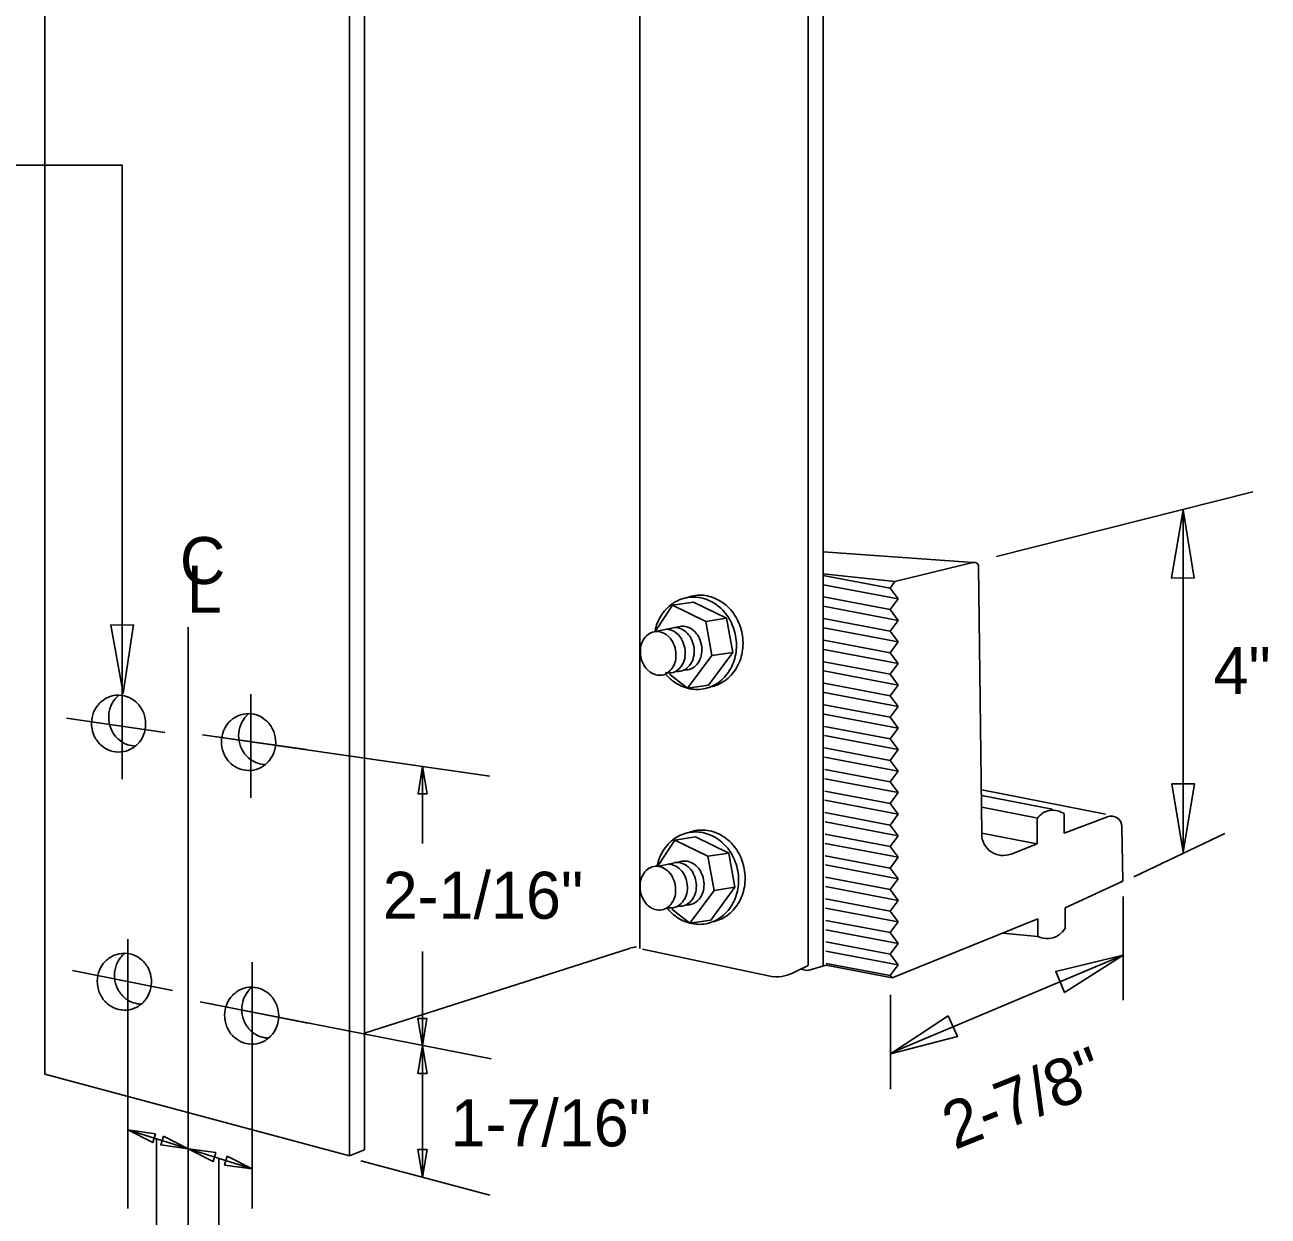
# Model space of a CAD drawing. Extents: x 12.3 to 19.6, y 5.9 to 16.2.
# Drawn here: x 17.486 to 19.073, y 9.472 to 10.993 of the extents above; entities that cross this region are included whole.
import ezdxf

# ---------------------------------------------------------------- set-up
doc = ezdxf.new("R2010")
doc.units = 0
for name, color, linetype in [('DETL-DIMS', 7, 'Continuous'), ('DETL-LINE', 7, 'Continuous'), ('DETL-NOTE', 7, 'Continuous')]:
    doc.layers.add(name, color=color, linetype=linetype)

msp = doc.modelspace()

# ---------------------------------------------------------------- linework, layer by layer
at = {"layer": 'DETL-DIMS'}
for p, q in [((17.61, 10.8139), (17.3733, 10.8139)), ((17.61, 10.8139), (17.61, 10.0298)), ((18.7263, 10.3141), (19.0536, 10.3965)), ((18.9648, 9.9352), (18.9648, 10.3742)), ((17.6945, 10.224), (17.6945, 9.4278)), ((17.7745, 10.1385), (17.7745, 10.0062)), ((17.5391, 10.1078), (17.6645, 10.0897)), ((17.7127, 10.0867), (18.0795, 10.0336)), ((17.9937, 9.9479), (17.9937, 10.0463)), ((19.0179, 9.9605), (18.9016, 9.9052)), ((18.8881, 9.88), (18.8881, 9.7477)), ((17.6174, 9.8256), (17.6174, 9.4821)), ((17.9937, 9.5218), (17.9937, 9.8101)), ((17.7761, 9.7964), (17.7761, 9.4821)), ((18.5909, 9.6803), (18.8881, 9.8051)), ((17.5465, 9.7855), (17.6743, 9.7601)), ((18.5909, 9.7546), (18.5909, 9.6343)), ((17.7097, 9.7456), (18.0811, 9.673)), ((17.6174, 9.5823), (17.7761, 9.5325)), ((17.6539, 9.5709), (17.6539, 9.3091)), ((17.7336, 9.5458), (17.7336, 9.4046)), ((18.0795, 9.499), (17.915, 9.5429))]:
    msp.add_line(p, q, dxfattribs=at)
for points in [[(18.9789, 10.2866), (18.9498, 10.2868), (18.9648, 10.3739)], [(17.6246, 10.2271), (17.5955, 10.2266), (17.6114, 10.1396)], [(17.9996, 10.0111), (17.9879, 10.0111), (17.9937, 10.0463)], [(18.9503, 10.0239), (18.9794, 10.0239), (18.9648, 9.9366)], [(18.8134, 9.7577), (18.8021, 9.7845), (18.8881, 9.8051)], [(17.9993, 9.7246), (17.9876, 9.7246), (17.9935, 9.6894)], [(18.6648, 9.728), (18.6766, 9.7014), (18.5909, 9.6794)], [(17.9994, 9.6543), (17.9877, 9.6543), (17.9935, 9.6894)], [(17.6527, 9.5773), (17.6492, 9.5661), (17.6174, 9.5822)], [(17.6628, 9.5742), (17.6593, 9.563), (17.6945, 9.5581)], [(17.7298, 9.5532), (17.7263, 9.542), (17.6945, 9.5581)], [(17.9995, 9.557), (17.9877, 9.557), (17.9937, 9.5218)], [(17.7443, 9.5486), (17.7408, 9.5374), (17.7761, 9.5325)]]:
    msp.add_lwpolyline(points, close=True, dxfattribs=at)
at = {"layer": 'DETL-LINE'}
for p, q in [((18.2711, 14.267), (18.2711, 9.8136)), ((18.486, 10.0267), (18.486, 13.1634)), ((17.9004, 9.5491), (17.9004, 13.1563)), ((17.9193, 9.5567), (17.9193, 13.1351)), ((17.5112, 9.6534), (17.5112, 13.1068)), ((18.5051, 9.7915), (18.5051, 13.0785)), ((18.6964, 10.3064), (18.5051, 10.3202)), ((18.6964, 10.3064), (18.5968, 10.2821)), ((18.5968, 10.2821), (18.5053, 10.2922)), ((18.5906, 10.2738), (18.5053, 10.29)), ((18.7075, 9.96), (18.7036, 10.3012)), ((18.6009, 10.26), (18.5054, 10.2782)), ((18.5906, 10.2738), (18.5968, 10.2821)), ((18.6009, 10.26), (18.5906, 10.2738)), ((18.3395, 10.256), (18.3129, 10.252)), ((18.3395, 10.256), (18.3819, 10.2353)), ((18.5906, 10.2463), (18.5055, 10.2625)), ((18.5906, 10.2463), (18.6009, 10.26)), ((18.2908, 10.2184), (18.3129, 10.252)), ((18.3129, 10.252), (18.3552, 10.2314)), ((18.6009, 10.2325), (18.5056, 10.2507)), ((18.6009, 10.2325), (18.5906, 10.2463)), ((18.3224, 10.2249), (18.2908, 10.2184)), ((18.3819, 10.2353), (18.3552, 10.2314)), ((18.3552, 10.2314), (18.3631, 10.1878)), ((18.3819, 10.2353), (18.3898, 10.1918)), ((18.5906, 10.2188), (18.5057, 10.2349)), ((18.6009, 10.2051), (18.5058, 10.2231)), ((18.5906, 10.2188), (18.6009, 10.2325)), ((18.5906, 10.1913), (18.5059, 10.2074)), ((18.6009, 10.2051), (18.5906, 10.2188)), ((18.3898, 10.1918), (18.3588, 10.1499)), ((18.3898, 10.1918), (18.3631, 10.1878)), ((18.6009, 10.1776), (18.506, 10.1956)), ((18.5906, 10.1913), (18.6009, 10.2051)), ((18.6009, 10.1776), (18.5906, 10.1913)), ((18.3631, 10.1878), (18.3321, 10.146)), ((18.5906, 10.1638), (18.5061, 10.1799)), ((18.5906, 10.1638), (18.6009, 10.1776)), ((18.3321, 10.146), (18.309, 10.1639)), ((18.6009, 10.1501), (18.5061, 10.1681)), ((18.6009, 10.1501), (18.5906, 10.1638)), ((18.3588, 10.1499), (18.3321, 10.146)), ((18.5906, 10.1363), (18.5063, 10.1524)), ((18.5906, 10.1363), (18.6009, 10.1501)), ((18.6009, 10.1226), (18.5063, 10.1406)), ((18.6009, 10.1226), (18.5906, 10.1363)), ((18.5906, 10.1089), (18.5065, 10.1249)), ((18.6009, 10.0951), (18.5065, 10.1131)), ((18.5906, 10.1089), (18.6009, 10.1226)), ((18.5906, 10.0814), (18.5067, 10.0973)), ((18.6009, 10.0951), (18.5906, 10.1089)), ((17.7127, 10.0867), (17.8454, 10.0676)), ((18.6009, 10.0676), (18.5067, 10.0855)), ((18.5906, 10.0814), (18.6009, 10.0951)), ((18.6009, 10.0676), (18.5906, 10.0814)), ((18.5906, 10.0539), (18.5069, 10.0698)), ((18.5906, 10.0539), (18.6009, 10.0676)), ((18.6009, 10.0402), (18.5069, 10.058)), ((18.6009, 10.0402), (18.5906, 10.0539)), ((18.5906, 10.0264), (18.5071, 10.0423)), ((18.5906, 10.0264), (18.6009, 10.0402)), ((18.486, 10.0267), (18.486, 9.7922)), ((18.6009, 10.0127), (18.5071, 10.0305)), ((18.6009, 10.0127), (18.5906, 10.0264)), ((18.5906, 9.9989), (18.5072, 10.0148)), ((18.6009, 9.9852), (18.5073, 10.003)), ((18.5906, 9.9989), (18.6009, 10.0127)), ((18.8658, 9.9852), (18.7075, 10.0162)), ((18.7976, 9.9916), (18.7075, 10.0092)), ((18.5906, 9.9714), (18.5074, 9.9872)), ((18.6009, 9.9852), (18.5906, 9.9989)), ((18.5906, 9.9714), (18.6009, 9.9852)), ((18.777, 9.9805), (18.7075, 9.9941)), ((18.813, 9.9611), (18.813, 9.9855)), ((18.6009, 9.9577), (18.5075, 9.9754)), ((18.6009, 9.9577), (18.5906, 9.9714)), ((18.7783, 9.9475), (18.7783, 9.9795)), ((18.868, 9.9819), (18.813, 9.9611)), ((18.8877, 9.8998), (18.8866, 9.9693)), ((18.3423, 9.9562), (18.3156, 9.9522)), ((18.3423, 9.9562), (18.3846, 9.9355)), ((18.5906, 9.944), (18.5076, 9.9597)), ((18.5906, 9.944), (18.6009, 9.9577)), ((18.7779, 9.9473), (18.7075, 9.9611)), ((18.2936, 9.9186), (18.3156, 9.9522)), ((18.3156, 9.9522), (18.3579, 9.9316)), ((18.6009, 9.9302), (18.5077, 9.9479)), ((18.6009, 9.9302), (18.5906, 9.944)), ((18.7783, 9.9475), (18.745, 9.9344)), ((18.3252, 9.9251), (18.2936, 9.9186)), ((18.3846, 9.9355), (18.3579, 9.9316)), ((18.3579, 9.9316), (18.3659, 9.888)), ((18.3846, 9.9355), (18.3925, 9.8919)), ((18.5906, 9.9165), (18.5078, 9.9322)), ((18.5906, 9.9165), (18.6009, 9.9302)), ((18.6009, 9.9027), (18.5079, 9.9204)), ((18.6009, 9.9027), (18.5906, 9.9165)), ((18.3925, 9.8919), (18.3616, 9.8501)), ((18.3925, 9.8919), (18.3659, 9.888)), ((18.5906, 9.889), (18.508, 9.9047)), ((18.6009, 9.8752), (18.5081, 9.8929)), ((18.5906, 9.889), (18.6009, 9.9027)), ((18.8877, 9.8998), (18.8139, 9.8658)), ((18.3659, 9.888), (18.3349, 9.8461)), ((18.5906, 9.8615), (18.5082, 9.8772)), ((18.6009, 9.8752), (18.5906, 9.889)), ((18.5906, 9.8615), (18.6009, 9.8752)), ((18.3349, 9.8461), (18.3118, 9.8641)), ((18.6009, 9.8478), (18.5083, 9.8654)), ((18.6009, 9.8478), (18.5906, 9.8615)), ((18.8139, 9.8658), (18.8139, 9.8389)), ((18.3616, 9.8501), (18.3349, 9.8461)), ((18.5906, 9.834), (18.5084, 9.8496)), ((18.5906, 9.834), (18.6009, 9.8478)), ((18.7792, 9.8518), (18.5932, 9.7765)), ((18.7792, 9.8518), (18.7792, 9.829)), ((18.6009, 9.8203), (18.5085, 9.8378)), ((18.6009, 9.8203), (18.5906, 9.834)), ((18.7792, 9.829), (18.7339, 9.8335)), ((18.258, 9.8139), (17.9193, 9.7055)), ((18.2743, 9.8128), (18.4412, 9.7778)), ((18.5906, 9.8065), (18.5086, 9.8221)), ((18.6009, 9.7928), (18.5087, 9.8103)), ((18.5906, 9.8065), (18.6009, 9.8203)), ((18.5906, 9.7791), (18.5088, 9.7946)), ((18.6009, 9.7928), (18.5906, 9.8065)), ((18.486, 9.7922), (18.4693, 9.784)), ((18.4855, 9.7858), (18.4758, 9.7872)), ((18.5088, 9.7926), (18.4855, 9.7858)), ((18.5932, 9.7765), (18.5088, 9.7926)), ((18.5906, 9.7791), (18.6009, 9.7928)), ((18.5906, 9.7791), (18.5932, 9.7765)), ((17.7097, 9.7456), (17.847, 9.7184)), ((17.9004, 9.5491), (17.5112, 9.6534)), ((17.9004, 9.5491), (17.9193, 9.5567))]:
    msp.add_line(p, q, dxfattribs=at)
for centre, radius, start, end in [((18.6981, 10.3012), 0.0055, 0, 108.2049), ((18.3395, 10.2159), 0.0465, 100.2985, 125.3838), ((18.3479, 10.2183), 0.0465, 100.2985, 111.3926), ((18.3395, 10.2159), 0.0465, 75.2131, 100.2985), ((18.3479, 10.2183), 0.0465, 75.2131, 100.2985), ((18.3377, 10.2093), 0.0533, 51.8022, 75.2131), ((18.3461, 10.2117), 0.0533, 51.8022, 75.2131), ((18.3434, 10.2104), 0.0533, 125.3838, 148.7948), ((18.334, 10.2046), 0.0593, 30.427, 51.8022), ((18.3424, 10.207), 0.0593, 30.427, 51.8022), ((18.3485, 10.2073), 0.0593, 148.7948, 168.1028), ((18.3159, 10.2052), 0.0183, 73.0064, 92.4483), ((18.3144, 10.2001), 0.0236, 49.0558, 73.0064), ((18.3257, 10.207), 0.0183, 73.0064, 100.2985), ((18.3241, 10.2019), 0.0236, 49.0558, 73.0064), ((18.3276, 10.2008), 0.0668, 10.2985, 30.427), ((18.336, 10.2033), 0.0668, 10.2985, 30.427), ((18.3003, 10.1936), 0.0286, 151.5411, 171.905), ((18.296, 10.196), 0.0236, 127.5906, 151.5411), ((18.2927, 10.2002), 0.0183, 100.2985, 127.5906), ((18.2927, 10.2002), 0.0183, 73.0064, 100.2985), ((18.2911, 10.1951), 0.0236, 49.0558, 73.0064), ((18.3045, 10.2031), 0.0183, 73.0064, 88.18), ((18.2879, 10.1914), 0.0286, 28.6919, 49.0558), ((18.303, 10.198), 0.0236, 49.0558, 73.0064), ((18.2997, 10.1943), 0.0286, 28.6919, 49.0558), ((18.2941, 10.1912), 0.0349, 10.2985, 28.6919), ((18.3111, 10.1964), 0.0286, 28.6919, 49.0558), ((18.3055, 10.1933), 0.0349, 10.2985, 28.6919), ((18.3209, 10.1981), 0.0286, 28.6919, 49.0558), ((18.3153, 10.1951), 0.0349, 10.2985, 28.6919), ((18.3276, 10.2008), 0.0668, 350.1699, 10.2985), ((18.336, 10.2033), 0.0668, 350.1699, 10.2985), ((18.3066, 10.1927), 0.0349, 171.905, 190.2985), ((18.2823, 10.1883), 0.0349, 10.2985, 28.6919), ((18.2823, 10.1883), 0.0349, 351.905, 10.2985), ((18.2941, 10.1912), 0.0349, 351.905, 10.2985), ((18.3055, 10.1933), 0.0349, 351.905, 10.2985), ((18.3153, 10.1951), 0.0349, 351.905, 10.2985), ((18.3434, 10.202), 0.0593, 328.7948, 350.1699), ((18.3066, 10.1927), 0.0349, 190.2985, 208.6919), ((18.301, 10.1897), 0.0286, 208.6919, 229.0558), ((18.2886, 10.1874), 0.0286, 331.5411, 351.905), ((18.3048, 10.188), 0.0236, 307.5906, 331.5411), ((18.3005, 10.1903), 0.0286, 331.5411, 351.905), ((18.3162, 10.19), 0.0236, 307.5906, 331.5411), ((18.3119, 10.1924), 0.0286, 331.5411, 351.905), ((18.326, 10.1918), 0.0236, 307.5906, 331.5411), ((18.3216, 10.1942), 0.0286, 331.5411, 351.905), ((18.335, 10.1996), 0.0593, 328.7948, 350.1699), ((18.2978, 10.1859), 0.0236, 229.0558, 253.0064), ((18.2962, 10.1808), 0.0183, 253.0064, 280.2985), ((18.2962, 10.1808), 0.0183, 280.2985, 307.5906), ((18.3494, 10.2022), 0.0593, 218.8502, 231.8022), ((18.3081, 10.1837), 0.0183, 256.2344, 280.2985), ((18.293, 10.1851), 0.0236, 307.5906, 331.5411), ((18.3081, 10.1837), 0.0183, 280.2985, 307.5906), ((18.3195, 10.1858), 0.0183, 261.8081, 280.2985), ((18.3195, 10.1858), 0.0183, 280.2985, 307.5906), ((18.3292, 10.1876), 0.0183, 264.5248, 280.2985), ((18.3292, 10.1876), 0.0183, 280.2985, 307.5906), ((18.3401, 10.1965), 0.0533, 305.3838, 328.7948), ((18.3485, 10.1989), 0.0533, 305.3838, 328.7948), ((18.3457, 10.1975), 0.0533, 231.8022, 255.2131), ((18.344, 10.1909), 0.0465, 255.2131, 280.2985), ((18.344, 10.1909), 0.0465, 280.2985, 305.3838), ((18.3524, 10.1933), 0.0465, 280.6187, 305.3838), ((17.6061, 10.1026), 0.0347, 118.398, 141.3012), ((17.6053, 10.1042), 0.0329, 94.8615, 118.398), ((17.6292, 10.1093), 0.0363, 141.3012, 163.3619), ((17.628, 10.1103), 0.0347, 129.3848, 141.3012), ((17.6053, 10.1042), 0.0329, 71.325, 94.8615), ((17.6047, 10.1025), 0.0347, 48.4218, 71.325), ((17.6036, 10.1014), 0.0363, 26.3611, 48.4218), ((17.6092, 10.1011), 0.0382, 163.3619, 184.8615), ((17.6073, 10.1017), 0.0363, 141.3012, 163.3619), ((17.6311, 10.1088), 0.0382, 163.3619, 184.8615), ((17.6019, 10.1005), 0.0382, 4.8615, 26.3611), ((17.7712, 10.0807), 0.0329, 94.8615, 118.398), ((17.7939, 10.0868), 0.0347, 129.3848, 141.3012), ((17.7712, 10.0807), 0.0329, 71.325, 94.8615), ((17.7706, 10.079), 0.0347, 48.4218, 71.325), ((17.6092, 10.1011), 0.0382, 184.8615, 206.3611), ((17.6311, 10.1088), 0.0382, 184.8615, 206.3611), ((17.6019, 10.1005), 0.0382, 343.3619, 4.8615), ((17.7733, 10.0781), 0.0363, 141.3012, 163.3619), ((17.772, 10.0791), 0.0347, 118.398, 141.3012), ((17.797, 10.0852), 0.0382, 163.3619, 184.8615), ((17.7952, 10.0858), 0.0363, 141.3012, 163.3619), ((17.7696, 10.0778), 0.0363, 26.3611, 48.4218), ((17.6075, 10.1003), 0.0363, 206.3611, 228.4218), ((17.6294, 10.1079), 0.0363, 206.3611, 228.4218), ((17.6283, 10.1068), 0.0347, 228.4218, 251.325), ((17.6038, 10.1), 0.0363, 321.3012, 343.3619), ((17.7751, 10.0776), 0.0382, 163.3619, 184.8615), ((17.797, 10.0852), 0.0382, 184.8615, 206.3611), ((17.7679, 10.077), 0.0382, 4.8615, 26.3611), ((17.7679, 10.077), 0.0382, 343.3619, 4.8615), ((17.6064, 10.0991), 0.0347, 228.4218, 251.325), ((17.6058, 10.0974), 0.0329, 251.325, 274.8615), ((17.6058, 10.0974), 0.0329, 274.8615, 298.398), ((17.6277, 10.1051), 0.0329, 251.325, 268.7325), ((17.605, 10.099), 0.0347, 298.398, 321.3012), ((17.7751, 10.0776), 0.0382, 184.8615, 206.3611), ((17.7953, 10.0844), 0.0363, 206.3611, 228.4218), ((17.7697, 10.0764), 0.0363, 321.3012, 343.3619), ((17.7734, 10.0767), 0.0363, 206.3611, 228.4218), ((17.7723, 10.0756), 0.0347, 228.4218, 251.325), ((17.7942, 10.0832), 0.0347, 228.4218, 251.325), ((17.7937, 10.0815), 0.0329, 251.325, 268.7325), ((17.7709, 10.0755), 0.0347, 298.398, 321.3012), ((17.7718, 10.0739), 0.0329, 251.325, 274.8615), ((17.7718, 10.0739), 0.0329, 274.8615, 298.398), ((18.7985, 9.9661), 0.0242, 53.1696, 146.3986), ((18.8729, 9.9691), 0.0137, 0.8619, 110.774), ((18.3462, 9.9106), 0.0533, 125.3838, 148.7948), ((18.3422, 9.9161), 0.0465, 100.2985, 125.3838), ((18.3506, 9.9185), 0.0465, 100.2985, 111.3926), ((18.3422, 9.9161), 0.0465, 75.2131, 100.2985), ((18.3506, 9.9185), 0.0465, 75.2131, 100.2985), ((18.3405, 9.9095), 0.0533, 51.8022, 75.2131), ((18.3489, 9.9119), 0.0533, 51.8022, 75.2131), ((18.3452, 9.9072), 0.0593, 30.427, 51.8022), ((18.735, 9.96), 0.0275, 180, 291.3921), ((18.3513, 9.9075), 0.0593, 148.7948, 168.1028), ((18.3368, 9.9048), 0.0593, 30.427, 51.8022), ((18.3387, 9.9034), 0.0668, 10.2985, 30.427), ((18.3073, 9.9033), 0.0183, 73.0064, 88.18), ((18.3187, 9.9054), 0.0183, 73.0064, 100.2985), ((18.3171, 9.9003), 0.0236, 49.0558, 73.0064), ((18.3285, 9.9072), 0.0183, 73.0064, 100.2985), ((18.3269, 9.902), 0.0236, 49.0558, 73.0064), ((18.3303, 9.901), 0.0668, 10.2985, 30.427), ((18.2999, 9.8938), 0.0286, 151.5411, 171.905), ((18.2955, 9.8962), 0.0236, 127.5906, 151.5411), ((18.2922, 9.9004), 0.0183, 100.2985, 127.5906), ((18.2922, 9.9004), 0.0183, 73.0064, 100.2985), ((18.2907, 9.8953), 0.0236, 49.0558, 73.0064), ((18.2875, 9.8916), 0.0286, 28.6919, 49.0558), ((18.2819, 9.8885), 0.0349, 10.2985, 28.6919), ((18.3057, 9.8982), 0.0236, 49.0558, 73.0064), ((18.3025, 9.8945), 0.0286, 28.6919, 49.0558), ((18.2969, 9.8914), 0.0349, 10.2985, 28.6919), ((18.3139, 9.8965), 0.0286, 28.6919, 49.0558), ((18.3083, 9.8935), 0.0349, 10.2985, 28.6919), ((18.3237, 9.8983), 0.0286, 28.6919, 49.0558), ((18.3181, 9.8953), 0.0349, 10.2985, 28.6919), ((18.3303, 9.901), 0.0668, 350.1699, 10.2985), ((18.3387, 9.9034), 0.0668, 350.1699, 10.2985), ((18.3062, 9.8929), 0.0349, 171.905, 190.2985), ((18.2819, 9.8885), 0.0349, 351.905, 10.2985), ((18.2969, 9.8914), 0.0349, 351.905, 10.2985), ((18.3083, 9.8935), 0.0349, 351.905, 10.2985), ((18.3244, 9.8944), 0.0286, 331.5411, 351.905), ((18.3181, 9.8953), 0.0349, 351.905, 10.2985), ((18.3377, 9.8998), 0.0593, 328.7948, 350.1699), ((18.3461, 9.9022), 0.0593, 328.7948, 350.1699), ((18.3062, 9.8929), 0.0349, 190.2985, 208.6919), ((18.3006, 9.8899), 0.0286, 208.6919, 229.0558), ((18.2925, 9.8853), 0.0236, 307.5906, 331.5411), ((18.2882, 9.8876), 0.0286, 331.5411, 351.905), ((18.3075, 9.8882), 0.0236, 307.5906, 331.5411), ((18.3032, 9.8905), 0.0286, 331.5411, 351.905), ((18.3189, 9.8902), 0.0236, 307.5906, 331.5411), ((18.3146, 9.8926), 0.0286, 331.5411, 351.905), ((18.3287, 9.892), 0.0236, 307.5906, 331.5411), ((18.2973, 9.8861), 0.0236, 229.0558, 253.0064), ((18.2958, 9.881), 0.0183, 253.0064, 280.2985), ((18.2958, 9.881), 0.0183, 280.2985, 307.5906), ((18.3522, 9.9024), 0.0593, 218.8502, 231.8022), ((18.3108, 9.8839), 0.0183, 256.2344, 280.2985), ((18.3108, 9.8839), 0.0183, 280.2985, 307.5906), ((18.3222, 9.886), 0.0183, 261.8081, 280.2985), ((18.3222, 9.886), 0.0183, 280.2985, 307.5906), ((18.332, 9.8878), 0.0183, 264.5248, 280.2985), ((18.332, 9.8878), 0.0183, 280.2985, 307.5906), ((18.3428, 9.8966), 0.0533, 305.3838, 328.7948), ((18.3512, 9.8991), 0.0533, 305.3838, 328.7948), ((18.3485, 9.8977), 0.0533, 231.8022, 255.2131), ((18.3468, 9.8911), 0.0465, 255.2131, 280.2985), ((18.3468, 9.8911), 0.0465, 280.2985, 305.3838), ((18.3552, 9.8935), 0.0465, 280.6187, 305.3838), ((18.7908, 9.854), 0.0275, 245.0714, 326.8004), ((18.2702, 9.7758), 0.0401, 94.8415, 107.7525), ((17.6147, 9.7723), 0.0363, 141.3012, 163.3619), ((17.6135, 9.7732), 0.0347, 118.398, 141.3012), ((17.6126, 9.7748), 0.0329, 94.8615, 118.398), ((17.6366, 9.7799), 0.0363, 141.3012, 163.3619), ((17.6354, 9.7809), 0.0347, 129.3848, 141.3012), ((17.6126, 9.7748), 0.0329, 71.325, 94.8615), ((17.6121, 9.7731), 0.0347, 48.4218, 71.325), ((17.611, 9.772), 0.0363, 26.3611, 48.4218), ((17.6165, 9.7717), 0.0382, 163.3619, 184.8615), ((17.6385, 9.7794), 0.0382, 163.3619, 184.8615), ((17.6093, 9.7711), 0.0382, 4.8615, 26.3611), ((18.4459, 9.8231), 0.0455, 264.0302, 300.9179), ((17.6165, 9.7717), 0.0382, 184.8615, 206.3611), ((17.6385, 9.7794), 0.0382, 184.8615, 206.3611), ((17.6368, 9.7785), 0.0363, 206.3611, 228.4218), ((17.6093, 9.7711), 0.0382, 343.3619, 4.8615), ((17.7752, 9.7315), 0.0329, 94.8615, 118.398), ((17.7979, 9.7376), 0.0347, 129.3848, 141.3012), ((17.7752, 9.7315), 0.0329, 71.325, 94.8615), ((17.7746, 9.7298), 0.0347, 48.4218, 71.325), ((17.6148, 9.7709), 0.0363, 206.3611, 228.4218), ((17.6357, 9.7774), 0.0347, 228.4218, 251.325), ((17.6124, 9.7696), 0.0347, 298.398, 321.3012), ((17.6111, 9.7706), 0.0363, 321.3012, 343.3619), ((17.7772, 9.7289), 0.0363, 141.3012, 163.3619), ((17.776, 9.7299), 0.0347, 118.398, 141.3012), ((17.801, 9.736), 0.0382, 163.3619, 184.8615), ((17.7991, 9.7366), 0.0363, 141.3012, 163.3619), ((17.7735, 9.7286), 0.0363, 26.3611, 48.4218), ((17.6138, 9.7697), 0.0347, 228.4218, 251.325), ((17.6132, 9.768), 0.0329, 251.325, 274.8615), ((17.6132, 9.768), 0.0329, 274.8615, 298.398), ((17.6351, 9.7757), 0.0329, 251.325, 268.7325), ((17.7791, 9.7284), 0.0382, 163.3619, 184.8615), ((17.801, 9.736), 0.0382, 184.8615, 206.3611), ((17.7718, 9.7278), 0.0382, 4.8615, 26.3611), ((17.7718, 9.7278), 0.0382, 343.3619, 4.8615), ((17.7791, 9.7284), 0.0382, 184.8615, 206.3611), ((17.7993, 9.7352), 0.0363, 206.3611, 228.4218), ((17.7737, 9.7272), 0.0363, 321.3012, 343.3619), ((17.7774, 9.7275), 0.0363, 206.3611, 228.4218), ((17.7763, 9.7264), 0.0347, 228.4218, 251.325), ((17.7982, 9.734), 0.0347, 228.4218, 251.325), ((17.7976, 9.7323), 0.0329, 251.325, 268.7325), ((17.7749, 9.7262), 0.0347, 298.398, 321.3012), ((17.7757, 9.7246), 0.0329, 251.325, 274.8615), ((17.7757, 9.7246), 0.0329, 274.8615, 298.398)]:
    msp.add_arc(centre, radius, start, end, dxfattribs=at)

# ---------------------------------------------------------------- texts
at = {"layer": 'DETL-NOTE'}
for s, p in [('C', (17.6838, 10.279)), ('L', (17.6926, 10.2424)), ('4"', (19.0035, 10.1387)), ('2-1/16"', (17.9428, 9.8517)), ('1-7/16"', (18.0293, 9.5612))]:
    msp.add_text(s, height=0.06, dxfattribs=at).set_placement(p)
msp.add_text('2-7/8"', height=0.06, rotation=21.7109, dxfattribs=at).set_placement((18.6731, 9.5564))

doc.saveas('drawing.dxf')
